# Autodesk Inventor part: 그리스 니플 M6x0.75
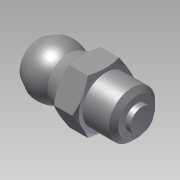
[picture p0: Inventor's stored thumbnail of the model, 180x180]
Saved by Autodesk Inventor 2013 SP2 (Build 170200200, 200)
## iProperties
Created: 2025-04
Part Number: 그리스 니플 M6x0.75
Material: Generic
Document SubType Name: Modeling
Designer: i
Density: 1 g/cm^3
변환 표준: STEP AP214IS
전처리기: Build: 200, Release: 2013 SP2 Update 6 - Date: Thu 07/17/2014
전송 단위: 밀리미터
불확실성: 0.01
Author: i
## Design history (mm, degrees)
node "그리스 니플 M6x0.751"
body "Solid1"
node "기준1"
